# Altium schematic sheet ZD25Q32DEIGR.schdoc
size 127 x 101 mm
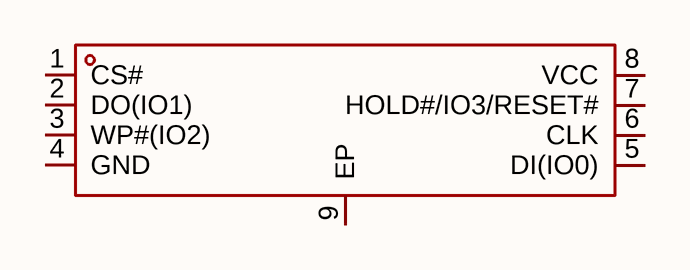
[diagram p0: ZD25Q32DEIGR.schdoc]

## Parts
U?  zd25q32deigr  [USON-8_L3.0-W2.0-P0.50-BL-EP-1]  (value not drawn)

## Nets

Not connected (* = marked no-connect by the designer): U? 1(CS#) 2(DO(IO1)) 3(WP#(IO2)) 4(GND) 5(DI(IO0)) 6(CLK) 7(HOLD#/IO3/RESET#) 8(VCC) 9(EP)

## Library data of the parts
U? = zd25q32deigr: SPI NOR FLASH,32Mbit,2.7~3.6V,USON2x3x0.45mm，Tape&Reel; Manufacturer: Zetta(澜智); AddInBom: yes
